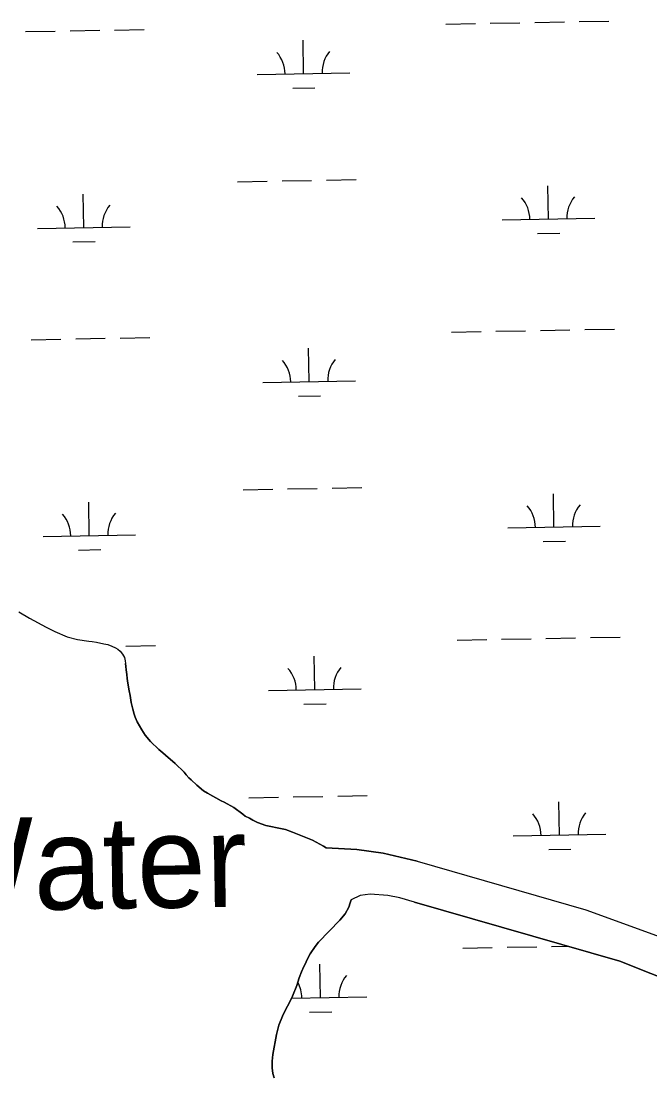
# Model space of a CAD drawing. Extents: x 3957609 to 3995875, y 234277 to 260273.
# Drawn here: x 3978279 to 3978958, y 243435 to 244572 of the extents above; entities that cross this region are included whole.
import ezdxf

# ---------------------------------------------------------------- set-up
doc = ezdxf.new("R2010")
doc.units = 0
for name, color, linetype in [('V-RIVR-IDEN', 7, 'Continuous'), ('V-TOPO-SHOR', 7, 'Continuous'), ('V-WETL-SWMP', 7, 'Continuous')]:
    doc.layers.add(name, color=color, linetype=linetype)

msp = doc.modelspace()

# ---------------------------------------------------------------- linework, layer by layer
at = {"layer": 'V-TOPO-SHOR'}
for points in [[(3978276.987, 243933.787), (3978288.349, 243926.805), (3978306.33, 243916.94), (3978315.561, 243912.469), (3978329.106, 243906.54), (3978340.216, 243903.589), (3978352.584, 243901.863), (3978356.144, 243901.656), (3978360.783, 243900.968), (3978368.655, 243899.149), (3978373.136, 243898.309), (3978377.296, 243896.702), (3978381.295, 243894.785), (3978383.904, 243893.195), (3978386.358, 243891.301), (3978388.94, 243887.856), (3978390.902, 243884.264), (3978391.777, 243880.535), (3978392.055, 243877.698)], [(3978608.812, 243678.88), (3978605.715, 243680.713), (3978593.951, 243686.968), (3978590.548, 243688.492), (3978572.296, 243695.789), (3978564.874, 243698.521), (3978561.319, 243699.426), (3978543.552, 243702.867), (3978534.584, 243706.051), (3978529.632, 243708.49), (3978526.07, 243710.631), (3978521.272, 243713.07), (3978518.636, 243715.214), (3978509.027, 243722.409), (3978498.498, 243728.209), (3978495.406, 243729.423), (3978480.543, 243737.666), (3978476.208, 243740.417), (3978468.919, 243746.391), (3978463.021, 243752.219), (3978460.539, 243754.364), (3978457.587, 243757.432), (3978455.41, 243760.352), (3978445.787, 243769.859), (3978435.24, 243778.899), (3978432.446, 243781.506), (3978427.951, 243784.873), (3978418.95, 243793.46), (3978413.353, 243800.523), (3978409.615, 243806.211), (3978404.78, 243814.821), (3978402.59, 243819.746), (3978401.335, 243823.287), (3978399.916, 243828.37), (3978398.326, 243835.768), (3978397.048, 243843.167), (3978395.936, 243848.406), (3978394.652, 243856.575), (3978393.698, 243861.507), (3978393.362, 243865.98), (3978392.715, 243871.069), (3978392.539, 243874.46), (3978392.055, 243877.698)], [(3978707.148, 243664.372), (3978670.252, 243673.148), (3978641.93, 243677.013), (3978608.812, 243678.88)], [(3978707.148, 243664.372), (3978889.369, 243611.874), (3979060.684, 243549.619)], [(3978552.758, 243430.429), (3978551.343, 243435.05), (3978550.38, 243441.063), (3978550.335, 243448.315), (3978551.22, 243455.417), (3978555.252, 243477.198), (3978557.816, 243487.087), (3978561.616, 243496.985), (3978563.442, 243501.01), (3978570.612, 243514.631), (3978572.439, 243518.653), (3978577.152, 243530.253), (3978579.726, 243538.447), (3978582.311, 243544.943), (3978584.746, 243550.514), (3978586.423, 243553.918), (3978587.943, 243557.475), (3978591.606, 243564.133), (3978596.802, 243572.341), (3978600.632, 243576.995), (3978623.479, 243600.585), (3978629.146, 243607.563), (3978633.115, 243614.84), (3978634.784, 243619.325), (3978635.692, 243622.724)], [(3978704.269, 243620.054), (3978688.454, 243624.615), (3978675.277, 243627.207), (3978656.18, 243628.797), (3978645.321, 243627.117), (3978635.692, 243622.724)], [(3978704.269, 243620.054), (3978926.01, 243556.222), (3979126.7, 243476.352), (3979285.112, 243422.272), (3979475.495, 243361.963), (3979654.731, 243298.907), (3979804.367, 243256.558), (3979945.23, 243223.829), (3980061.073, 243192.229), (3980280.041, 243147.982), (3980314.134, 243137.535), (3980323.19, 243133.041), (3980327.119, 243130.039), (3980328.939, 243126.125), (3980330.461, 243121.609), (3980330.471, 243117.692), (3980329.582, 243113.168), (3980245.137, 243000.724)]]:
    msp.add_lwpolyline(points, dxfattribs=at)
at = {"layer": 'V-WETL-SWMP'}
for p, q in [((3978380.217, 244561.906), (3978412.212, 244562.488)), ((3978738.066, 244568.413), (3978770.061, 244568.995)), ((3978786.058, 244569.286), (3978818.053, 244569.868)), ((3978834.05, 244570.158), (3978866.045, 244570.74)), ((3978882.042, 244571.031), (3978914.037, 244571.613)), ((3978284.233, 244560.161), (3978316.228, 244560.743)), ((3978332.225, 244561.034), (3978364.22, 244561.615)), ((3978584.422, 244514.869), (3978583.768, 244550.863)), ((3978534.43, 244513.96), (3978634.414, 244515.778)), ((3978572.705, 244499.222), (3978596.701, 244499.659)), ((3978513.125, 244398.122), (3978545.119, 244398.703)), ((3978561.117, 244398.994), (3978593.111, 244399.576)), ((3978609.109, 244399.867), (3978641.104, 244400.449)), ((3978848.757, 244357.787), (3978848.103, 244393.781)), ((3978346.932, 244348.662), (3978346.278, 244384.656)), ((3978798.766, 244356.878), (3978898.749, 244358.696)), ((3978296.941, 244347.753), (3978396.924, 244349.571)), ((3978837.04, 244342.14), (3978861.036, 244342.576)), ((3978335.215, 244333.015), (3978359.211, 244333.452)), ((3978744.114, 244235.793), (3978776.109, 244236.375)), ((3978792.106, 244236.666), (3978824.101, 244237.248)), ((3978840.098, 244237.538), (3978872.093, 244238.12)), ((3978888.09, 244238.411), (3978920.085, 244238.993)), ((3978290.281, 244227.541), (3978322.276, 244228.123)), ((3978338.273, 244228.414), (3978370.268, 244228.995)), ((3978386.265, 244229.286), (3978418.26, 244229.868)), ((3978590.47, 244182.249), (3978589.816, 244218.243)), ((3978540.478, 244181.34), (3978640.462, 244183.158)), ((3978578.753, 244166.602), (3978602.749, 244167.039)), ((3978519.173, 244065.502), (3978551.167, 244066.083)), ((3978567.165, 244066.374), (3978599.16, 244066.956)), ((3978615.157, 244067.247), (3978647.152, 244067.829)), ((3978352.98, 244016.042), (3978352.326, 244052.036)), ((3978854.806, 244025.167), (3978854.151, 244061.161)), ((3978302.989, 244015.133), (3978402.972, 244016.951)), ((3978804.814, 244024.258), (3978904.797, 244026.076)), ((3978843.088, 244009.52), (3978867.084, 244009.956)), ((3978341.263, 244000.395), (3978365.259, 244000.832)), ((3978750.162, 243903.173), (3978782.157, 243903.755)), ((3978798.154, 243904.046), (3978830.149, 243904.627)), ((3978846.146, 243904.918), (3978878.141, 243905.5)), ((3978894.138, 243905.791), (3978926.133, 243906.373)), ((3978392.313, 243896.666), (3978424.308, 243897.248)), ((3978596.518, 243849.629), (3978595.864, 243885.623)), ((3978546.526, 243848.72), (3978646.51, 243850.538)), ((3978584.801, 243833.982), (3978608.797, 243834.419)), ((3978525.221, 243732.881), (3978557.216, 243733.463)), ((3978573.213, 243733.754), (3978605.208, 243734.336)), ((3978621.205, 243734.627), (3978653.2, 243735.209)), ((3978860.854, 243692.547), (3978860.199, 243728.541)), ((3978810.862, 243691.638), (3978910.845, 243693.456)), ((3978849.136, 243676.9), (3978873.132, 243677.336)), ((3978756.21, 243570.553), (3978788.205, 243571.135)), ((3978804.202, 243571.426), (3978836.197, 243572.007)), ((3978852.194, 243572.298), (3978869.096, 243572.606)), ((3978602.566, 243517.009), (3978601.912, 243553.003)), ((3978571.435, 243516.443), (3978652.558, 243517.918)), ((3978590.849, 243501.362), (3978614.845, 243501.799))]:
    msp.add_line(p, q, dxfattribs=at)
for points in [[(3978276.987, 243933.787), (3978288.349, 243926.806), (3978306.33, 243916.94), (3978315.56, 243912.469), (3978329.106, 243906.54), (3978340.217, 243903.59), (3978352.584, 243901.862), (3978356.144, 243901.655), (3978360.782, 243900.968), (3978368.656, 243899.15), (3978373.136, 243898.31), (3978377.295, 243896.701), (3978381.295, 243894.784), (3978383.905, 243893.196), (3978386.357, 243891.302), (3978388.94, 243887.856), (3978390.902, 243884.265), (3978391.777, 243880.534), (3978392.056, 243877.698), (3978392.539, 243874.461), (3978392.714, 243871.068), (3978393.362, 243865.98), (3978393.697, 243861.507), (3978394.653, 243856.575), (3978395.936, 243848.405), (3978397.048, 243843.166), (3978398.327, 243835.767), (3978399.915, 243828.37), (3978401.334, 243823.287), (3978402.59, 243819.746), (3978404.78, 243814.821), (3978409.615, 243806.21), (3978413.353, 243800.523), (3978418.95, 243793.459), (3978427.951, 243784.873), (3978432.446, 243781.505), (3978435.239, 243778.899)], [(3978435.239, 243778.899), (3978445.786, 243769.859), (3978455.41, 243760.351), (3978457.588, 243757.432), (3978460.538, 243754.364), (3978463.02, 243752.219), (3978468.918, 243746.391), (3978476.207, 243740.417), (3978480.544, 243737.666), (3978495.406, 243729.424), (3978498.499, 243728.208), (3978509.027, 243722.408), (3978518.637, 243715.214), (3978521.273, 243713.07), (3978526.071, 243710.63), (3978529.632, 243708.491), (3978534.585, 243706.052), (3978543.553, 243702.866), (3978561.318, 243699.425), (3978564.873, 243698.52), (3978572.296, 243695.788), (3978590.547, 243688.492), (3978593.951, 243686.969), (3978605.715, 243680.714), (3978608.812, 243678.881), (3978641.929, 243677.013), (3978670.252, 243673.148), (3978707.149, 243664.372), (3978889.369, 243611.874), (3979060.685, 243549.619)], [(3979126.7, 243476.351), (3978926.01, 243556.222), (3978704.269, 243620.054), (3978688.454, 243624.615), (3978675.278, 243627.208), (3978656.18, 243628.796), (3978645.321, 243627.118), (3978635.691, 243622.724), (3978634.785, 243619.324), (3978633.115, 243614.839), (3978629.147, 243607.563), (3978623.48, 243600.586), (3978600.632, 243576.994), (3978596.803, 243572.342), (3978591.606, 243564.133), (3978587.943, 243557.476), (3978586.422, 243553.918), (3978584.745, 243550.513), (3978582.31, 243544.944), (3978579.726, 243538.448), (3978577.152, 243530.254), (3978572.439, 243518.653), (3978570.612, 243514.631), (3978563.442, 243501.009), (3978561.615, 243496.986), (3978557.817, 243487.088), (3978555.253, 243477.197), (3978551.219, 243455.417), (3978550.336, 243448.314), (3978550.38, 243441.062), (3978551.342, 243435.05), (3978552.758, 243430.43)]]:
    msp.add_lwpolyline(points, dxfattribs=at)
for centre, start, end in [((3978529.18, 244514.339), 0.269879, 41.813537), ((3978639.647, 244516.348), 140.269876, 181.813534), ((3978793.515, 244357.257), 0.269879, 41.813537), ((3978903.983, 244359.266), 140.269876, 181.813534), ((3978291.69, 244348.132), 0.269879, 41.813537), ((3978402.158, 244350.141), 140.269876, 181.813534), ((3978535.228, 244181.719), 0.269879, 41.813537), ((3978645.695, 244183.728), 140.269876, 181.813534), ((3978408.206, 244017.521), 140.269876, 181.813534), ((3978799.563, 244024.637), 0.269879, 41.813537), ((3978910.031, 244026.646), 140.269876, 181.813534), ((3978297.738, 244015.512), 0.269879, 41.813537), ((3978541.276, 243849.099), 0.269879, 41.813537), ((3978651.743, 243851.108), 140.269876, 181.813534), ((3978805.611, 243692.017), 0.269879, 41.813537), ((3978916.079, 243694.026), 140.269876, 181.813534), ((3978657.791, 243518.488), 140.269876, 181.813534), ((3978547.324, 243516.479), 0.269879, 28.910227)]:
    msp.add_arc(centre, 35.246, start, end, dxfattribs=at)

# ---------------------------------------------------------------- texts
at = {"layer": 'V-RIVR-IDEN'}
msp.add_text('Water', height=99.9998, rotation=0.902342, dxfattribs=at).set_placement((3978167.278, 243609.806))

doc.saveas('drawing.dxf')
